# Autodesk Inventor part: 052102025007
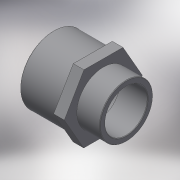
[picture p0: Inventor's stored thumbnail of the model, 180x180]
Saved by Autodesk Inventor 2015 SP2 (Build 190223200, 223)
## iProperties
Created: 2017-10
Part Number: 052102025007
Material: Generic
Description: PLASSON SOCKET NIPPLE THR-CE 32(25)-3/4"
Document SubType Name: Modeling
Designer: KIM
Density: 1 g/cm^3
Appearance: Default
Author: KIM
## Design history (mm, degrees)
derived "052102.ipt"
feature "Solid1::052102.ipt"
tag "TaggingFeature1"
body "Solid1"
other parameters: "d0" = 51, "d2" = 36, "d13" = 0, "d14" = 0.25, "d17" = 22, "d18" = 20.4, "d19" = 32, "d20" = 25, "d21" = 26.441, "d22" = 19, "d23" = 23.75, "d24" = 21.1528, "d25" = 17, "d26" = -22, "d_" = 25, "R_" = 26.441, "C_" = 36, "B_" = 12, "L_" = 22, "lt_" = 17, "H_" = 51, "D_" = 32, "l_" = 19
